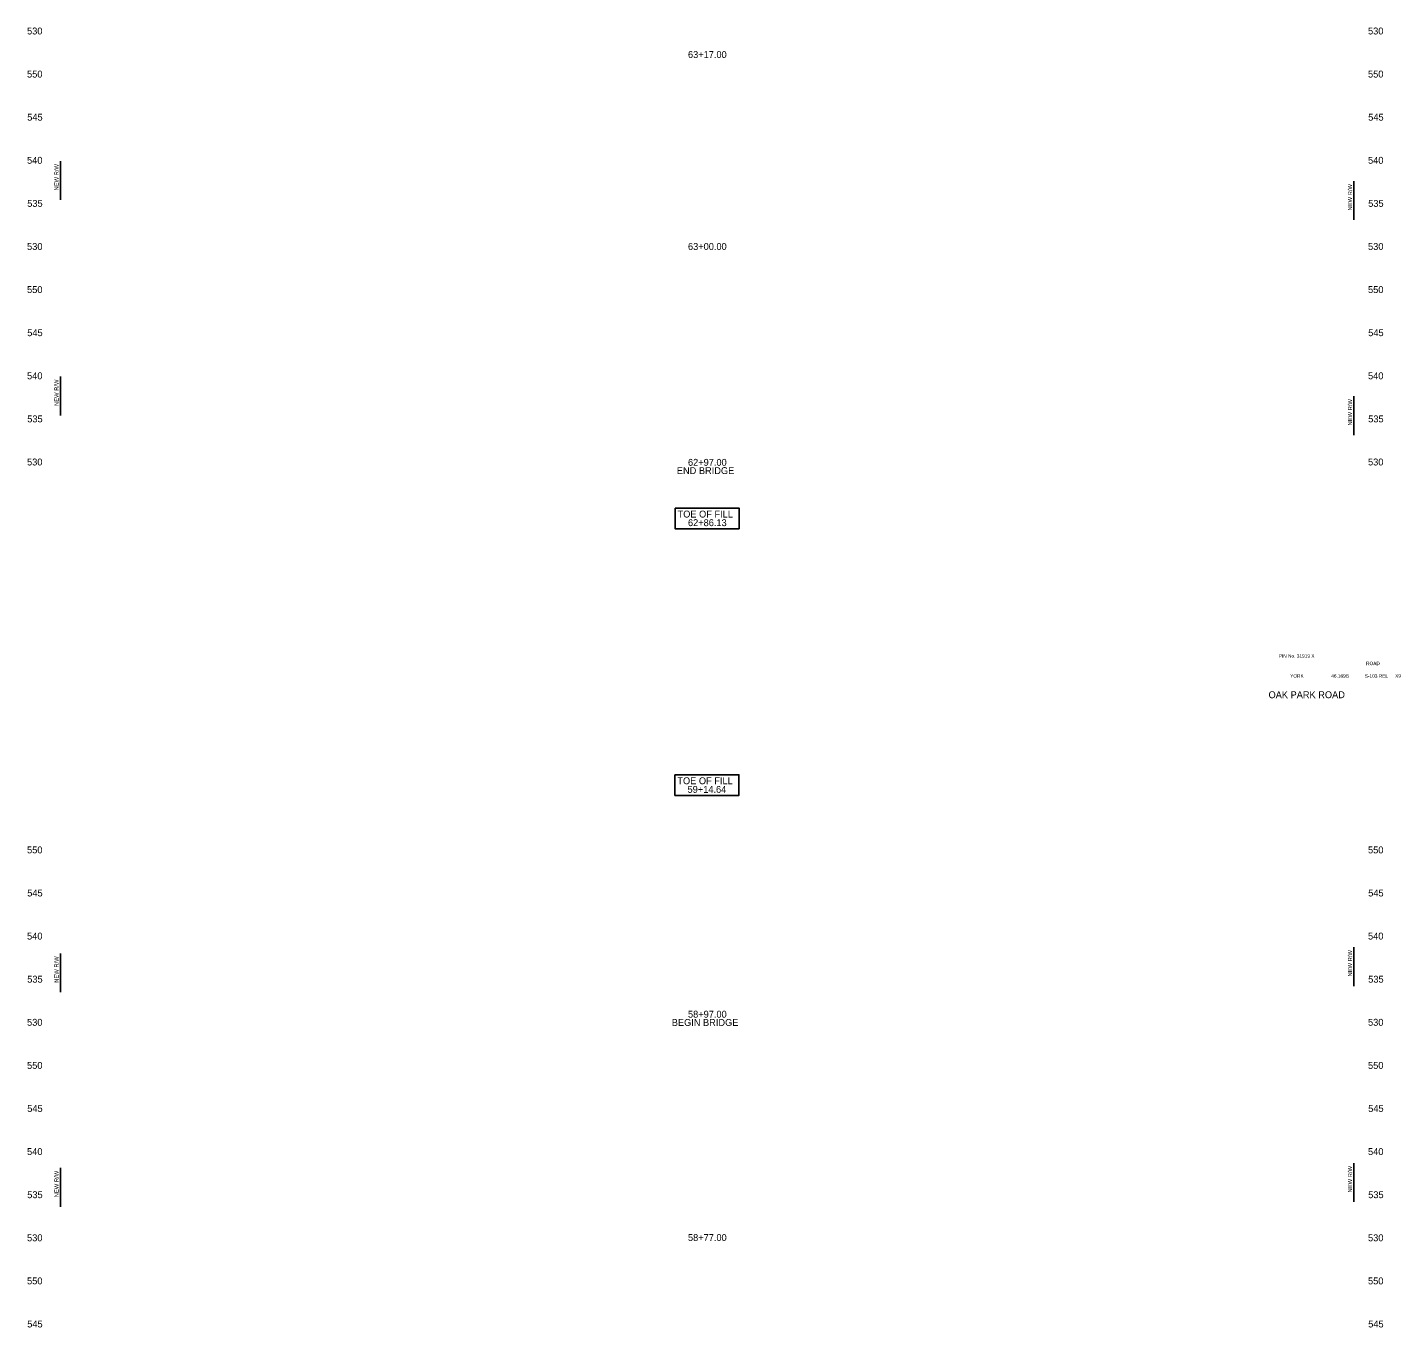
# Model space of a CAD drawing. Extents: x 1001 to 1161, y 1005 to 3518.
# Drawn here: x 1001.2 to 1160.4, y 1945.1 to 2095.9 of the extents above; entities that cross this region are included whole.
import ezdxf

# ---------------------------------------------------------------- set-up
doc = ezdxf.new("R2010")
doc.units = 0
for name, color, linetype in [('RD_SHT_TX', 7, 'Continuous'), ('RD_XS_NewRW', 7, 'Continuous'), ('RD_XS_TX_Elev_EX', 7, 'Continuous'), ('RD_XS_TX_Notes', 7, 'Continuous'), ('RD_XS_TX_Station', 7, 'Continuous')]:
    doc.layers.add(name, color=color, linetype=linetype)

msp = doc.modelspace()

# ---------------------------------------------------------------- linework, layer by layer
at = {"layer": 'RD_XS_NewRW'}
for p, q in [((1005, 2080.4), (1005, 2075.9)), ((1155, 2078.08), (1155, 2073.58)), ((1005, 2055.4), (1005, 2050.9)), ((1155, 2053.13), (1155, 2048.63)), ((1155, 1989.21), (1155, 1984.71)), ((1005, 1988.49), (1005, 1983.99)), ((1005, 1963.6), (1005, 1959.1)), ((1155, 1964.16), (1155, 1959.66))]:
    msp.add_line(p, q, dxfattribs=at)
at = {"layer": 'RD_XS_TX_Notes'}
for points in [[(1076.28, 2040.16), (1083.7, 2040.16), (1083.7, 2037.76), (1076.28, 2037.76)], [(1076.26, 2009.22), (1083.68, 2009.22), (1083.68, 2006.82), (1076.26, 2006.82)]]:
    msp.add_lwpolyline(points, close=True, dxfattribs=at)

# ---------------------------------------------------------------- texts
at = {"layer": 'RD_SHT_TX'}
for s, height, p in [('PIN No. 31919 X', 0.4, (1146.29, 2022.8)), ('ROAD', 0.4, (1156.41, 2021.93)), ('YORK', 0.4, (1147.61, 2020.48)), ('46.169B', 0.4, (1152.37, 2020.48)), ('S-103 REL', 0.4, (1156.26, 2020.48)), ('X9', 0.4, (1159.78, 2020.48)), ('OAK PARK ROAD', 0.8, (1145.1, 2018.1))]:
    msp.add_text(s, height=height, dxfattribs=at).set_placement(p)
at = {"layer": 'RD_XS_NewRW'}
for p in [(1004.8, 2077), (1154.8, 2074.68), (1004.8, 2052), (1154.8, 2049.73), (1154.8, 1985.81), (1004.8, 1985.09), (1154.8, 1960.76), (1004.8, 1960.2)]:
    msp.add_text('NEW R/W ', height=0.488, rotation=90, dxfattribs=at).set_placement(p)
at = {"layer": 'RD_XS_TX_Elev_EX'}
for s, p in [('530', (1001.14, 2095.1)), ('530', (1156.64, 2095.1)), ('550', (1001.14, 2090.1)), ('550', (1156.64, 2090.1)), ('545', (1001.16, 2085.1)), ('545', (1156.66, 2085.1)), ('540', (1001.14, 2080.1)), ('540', (1156.64, 2080.1)), ('535', (1001.16, 2075.1)), ('535', (1156.66, 2075.1)), ('530', (1001.14, 2070.1)), ('530', (1156.64, 2070.1)), ('550', (1001.14, 2065.1)), ('550', (1156.64, 2065.1)), ('545', (1001.16, 2060.1)), ('545', (1156.66, 2060.1)), ('540', (1001.14, 2055.1)), ('540', (1156.64, 2055.1)), ('535', (1001.16, 2050.1)), ('535', (1156.66, 2050.1)), ('530', (1001.14, 2045.1)), ('530', (1156.64, 2045.1)), ('550', (1001.14, 2000.1)), ('550', (1156.64, 2000.1)), ('545', (1001.16, 1995.1)), ('545', (1156.66, 1995.1)), ('540', (1001.14, 1990.1)), ('540', (1156.64, 1990.1)), ('535', (1001.16, 1985.1)), ('535', (1156.66, 1985.1)), ('530', (1001.14, 1980.1)), ('530', (1156.64, 1980.1)), ('550', (1001.14, 1975.1)), ('550', (1156.64, 1975.1)), ('545', (1001.16, 1970.1)), ('545', (1156.66, 1970.1)), ('540', (1001.14, 1965.1)), ('540', (1156.64, 1965.1)), ('535', (1001.16, 1960.1)), ('535', (1156.66, 1960.1)), ('530', (1001.14, 1955.1)), ('530', (1156.64, 1955.1)), ('550', (1001.14, 1950.1)), ('550', (1156.64, 1950.1)), ('545', (1001.16, 1945.1)), ('545', (1156.66, 1945.1))]:
    msp.add_text(s, height=0.8, dxfattribs=at).set_placement(p)
at = {"layer": 'RD_XS_TX_Notes'}
for s, p in [('TOE OF FILL', (1076.57, 2039.06)), ('62+86.13', (1077.78, 2038.06)), ('TOE OF FILL', (1076.55, 2008.12)), ('59+14.64', (1077.73, 2007.12))]:
    msp.add_text(s, height=0.8, dxfattribs=at).set_placement(p)
at = {"layer": 'RD_XS_TX_Station'}
for s, p in [('63+17.00', (1077.78, 2092.37)), ('63+00.00', (1077.78, 2070.1)), ('END BRIDGE', (1076.49, 2044.1)), ('62+97.00', (1077.78, 2045.06)), ('BEGIN BRIDGE', (1075.9, 1980.08)), ('58+97.00', (1077.78, 1981.04)), ('58+77.00', (1077.78, 1955.13))]:
    msp.add_text(s, height=0.8, dxfattribs=at).set_placement(p)

doc.saveas('drawing.dxf')
